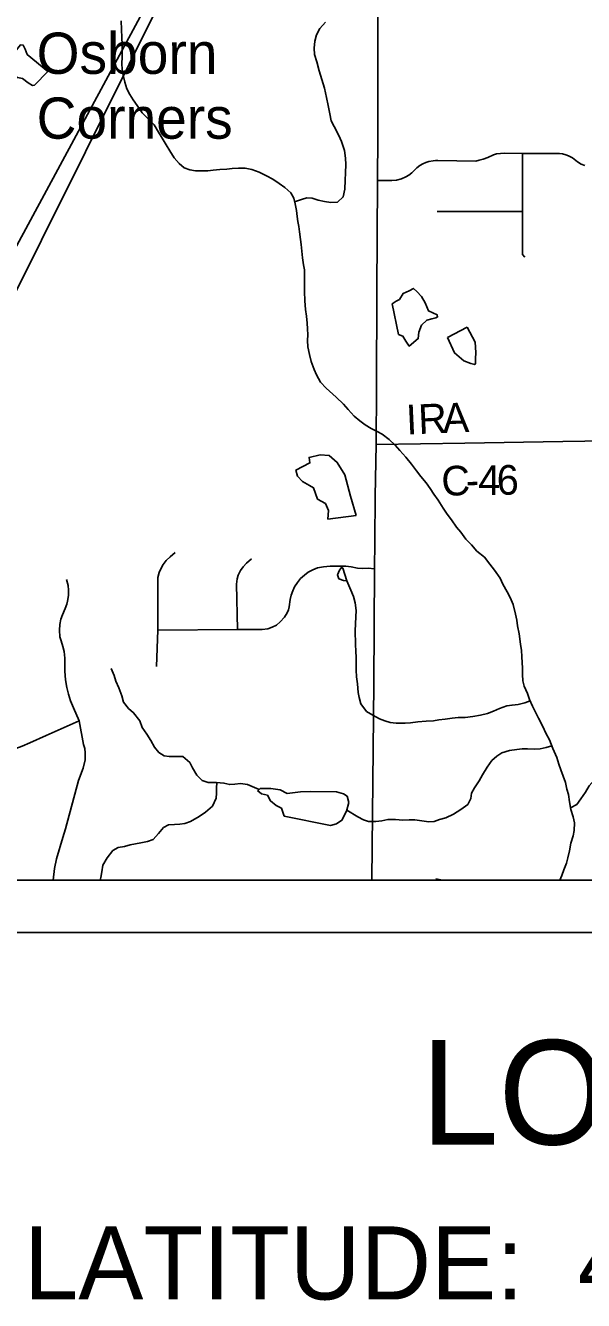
# Model space of a CAD drawing. Extents: x 0 to 34, y 0 to 22.
# Drawn here: x 3.669 to 4.739, y 13.295 to 15.737 of the extents above; entities that cross this region are included whole.
import ezdxf

# ---------------------------------------------------------------- set-up
doc = ezdxf.new("R2010")
doc.units = 0
for name, color, linetype in [('Default', 7, 'Continuous'), ('GM_X_County_Road', 7, 'Continuous'), ('GM_X_County_Road_Text', 7, 'Continuous'), ('GM_X_Minor_Lake', 7, 'Continuous'), ('GM_X_Minor_River', 7, 'Continuous'), ('GM_X_Township_Road', 7, 'Continuous'), ('GM_X_Unincorporated_Text', 7, 'Continuous'), ('SH_Cut_Line', 7, 'Continuous'), ('SH_Data', 7, 'Continuous'), ('SH_Text', 7, 'Continuous')]:
    doc.layers.add(name, color=color, linetype=linetype)

msp = doc.modelspace()

# ---------------------------------------------------------------- linework, layer by layer
at = {"layer": 'Default'}
msp.add_lwpolyline([(3.2815, 15.7537), (3.2811, 15.7294), (3.2832, 14.8896), (3.2841, 14.501), (3.2822, 14.2781), (3.2808, 14.1155), (3.2807, 14.1), (8.4439, 14.1), (8.4391, 14.4529), (8.4328, 14.555), (8.4328, 14.5554), (8.4608, 15.4787), (8.4608, 15.9241)], dxfattribs=at)
at = {"layer": 'GM_X_County_Road'}
for points in [[(4.3329, 14.1), (4.3329, 14.1015), (4.3366, 14.4752), (4.338, 14.6961), (4.3387, 14.7484), (4.3392, 14.8357), (4.3412, 14.9346), (4.3421, 15.043), (4.3424, 15.2273), (4.3441, 15.44), (4.3442, 15.525), (4.3442, 15.6692), (4.3448, 15.8518)], [(4.3412, 14.9346), (4.511, 14.937), (4.6987, 14.9398), (4.9098, 14.943), (5.086, 14.9444), (5.2239, 14.9463), (5.3069, 14.9479), (5.4298, 14.9489), (5.5067, 14.9509), (5.635, 14.953), (5.7464, 14.9549), (5.7732, 14.955), (5.875, 14.9557)]]:
    msp.add_lwpolyline(points, dxfattribs=at)
at = {"layer": 'GM_X_Minor_Lake'}
for points in [[(3.6727, 15.6811), (3.6688, 15.6914), (3.6653, 15.6989), (3.66, 15.7), (3.6353, 15.6682), (3.6403, 15.6531), (3.6465, 15.6421), (3.6541, 15.6373), (3.6636, 15.6351), (3.6747, 15.6268), (3.6831, 15.622), (3.6865, 15.6224), (3.7121, 15.6488)], [(3.7121, 15.6488), (3.6727, 15.6811)], [(4.3838, 15.1449), (4.3925, 15.142), (4.3979, 15.1321), (4.4048, 15.1227), (4.4218, 15.1373), (4.4228, 15.1495), (4.4284, 15.1628), (4.4385, 15.1724), (4.448, 15.1752), (4.4556, 15.1768), (4.459, 15.1787), (4.4582, 15.1825), (4.4414, 15.1903), (4.4352, 15.2058), (4.4283, 15.2175), (4.4191, 15.2273), (4.4126, 15.2333), (4.4043, 15.2287), (4.3933, 15.2237), (4.3858, 15.2122), (4.3794, 15.2091), (4.3718, 15.2037)], [(4.3718, 15.2037), (4.3838, 15.1449)], [(4.4779, 15.139), (4.4911, 15.1098), (4.5094, 15.0948), (4.5228, 15.0893), (4.53, 15.0874), (4.5315, 15.0897), (4.5314, 15.0981), (4.5321, 15.1106), (4.5311, 15.13), (4.5153, 15.1591)], [(4.5153, 15.1591), (4.4779, 15.139)], [(4.303, 14.7981), (4.2921, 14.8352), (4.2811, 14.8761), (4.2668, 14.8999), (4.2515, 14.9131), (4.2341, 14.9148), (4.2129, 14.9097), (4.2145, 14.8991), (4.1876, 14.8855), (4.1908, 14.8738), (4.2004, 14.8632), (4.2133, 14.8561), (4.221, 14.8516), (4.2291, 14.8297), (4.244, 14.8211), (4.2498, 14.8082), (4.2488, 14.7911)], [(4.2488, 14.7911), (4.303, 14.7981)], [(4.2774, 14.6976), (4.2747, 14.6987), (4.271, 14.6937), (4.2673, 14.6849), (4.27, 14.6774), (4.2784, 14.6736), (4.2852, 14.6733)], [(4.2852, 14.6733), (4.2774, 14.6976)], [(4.2541, 14.2046), (4.2655, 14.2081), (4.2757, 14.2147), (4.2843, 14.2319), (4.2887, 14.2486), (4.2855, 14.2608), (4.2786, 14.2656), (4.2653, 14.2693), (4.2148, 14.27), (4.1966, 14.2694), (4.1709, 14.2658), (4.1575, 14.2732), (4.1397, 14.2753), (4.1192, 14.2759), (4.1143, 14.2709), (4.1215, 14.2657), (4.1329, 14.2627), (4.1391, 14.2518), (4.1498, 14.2432), (4.1597, 14.2379), (4.1652, 14.2224)], [(4.1652, 14.2224), (4.2541, 14.2046)]]:
    msp.add_lwpolyline(points, dxfattribs=at)
at = {"layer": 'GM_X_Minor_River'}
for points in [[(4.2039, 15.2272), (4.2038, 15.2428), (4.2037, 15.2553), (4.2039, 15.269), (4.2023, 15.2785), (4.1999, 15.2921), (4.1974, 15.3172), (4.1966, 15.327), (4.1945, 15.3415), (4.1929, 15.3521), (4.1913, 15.3616), (4.1901, 15.371), (4.1885, 15.3824), (4.1861, 15.3949), (4.1833, 15.4063), (4.1775, 15.4161), (4.1661, 15.4263), (4.1557, 15.4342), (4.1435, 15.4424), (4.1309, 15.4491), (4.1172, 15.4558), (4.1031, 15.461), (4.0906, 15.4632), (4.0777, 15.4638), (4.0655, 15.463), (4.0549, 15.4617), (4.042, 15.4608), (4.0291, 15.4596), (4.0185, 15.4587), (3.9954, 15.4585), (3.984, 15.4603), (3.9737, 15.4644), (3.9641, 15.4723), (3.9546, 15.4832), (3.9461, 15.4964), (3.9388, 15.5081), (3.9314, 15.521), (3.9245, 15.5323), (3.9157, 15.5463), (3.9049, 15.5572), (3.8927, 15.5696), (3.8831, 15.5836), (3.8758, 15.5945), (3.8696, 15.6047), (3.8638, 15.6157), (3.8599, 15.6282), (3.8564, 15.6415), (3.8547, 15.6528), (3.8543, 15.6635), (3.8545, 15.6764), (3.8548, 15.6908), (3.8547, 15.7003), (3.8542, 15.7136), (3.8537, 15.7288), (3.8528, 15.7455)], [(4.1851, 15.3991), (4.1981, 15.4038), (4.2087, 15.4069), (4.2186, 15.4059), (4.23, 15.4022), (4.2426, 15.3997), (4.2544, 15.3979), (4.2669, 15.3987), (4.2782, 15.4083), (4.2811, 15.4236), (4.2817, 15.4403), (4.2827, 15.4544), (4.2833, 15.4703), (4.2824, 15.4825), (4.2804, 15.4973), (4.2749, 15.5143), (4.2695, 15.526), (4.261, 15.5431), (4.2552, 15.554), (4.2524, 15.5677), (4.2493, 15.5836), (4.2461, 15.5991), (4.2421, 15.6166), (4.237, 15.6333), (4.2323, 15.6499), (4.2273, 15.667), (4.2233, 15.6814), (4.2225, 15.6935), (4.2235, 15.7068), (4.2268, 15.7186), (4.2335, 15.7312), (4.244, 15.7431)], [(4.6929, 14.1), (4.6967, 14.1089), (4.7008, 14.1196), (4.7056, 14.1325), (4.7086, 14.1428), (4.7115, 14.1565), (4.7144, 14.171), (4.7184, 14.1847), (4.7206, 14.195), (4.7212, 14.2098), (4.7185, 14.2215), (4.7142, 14.2352), (4.7114, 14.2503), (4.7097, 14.264), (4.7066, 14.2746), (4.7038, 14.2871), (4.6953, 14.3113), (4.6914, 14.3219), (4.6871, 14.3352), (4.6797, 14.3519), (4.6731, 14.3685), (4.6666, 14.3817), (4.6604, 14.3946), (4.6523, 14.4101), (4.6407, 14.4335), (4.6349, 14.446), (4.631, 14.4574), (4.6251, 14.4714), (4.6224, 14.4816), (4.6219, 14.4941), (4.6218, 14.5059), (4.6209, 14.5169), (4.6205, 14.5279), (4.6196, 14.5408), (4.618, 14.5515), (4.6167, 14.5625), (4.6151, 14.572), (4.6123, 14.5871), (4.6107, 14.5981), (4.6083, 14.6095), (4.6036, 14.6277), (4.5982, 14.6413), (4.5924, 14.6523), (4.5839, 14.6666), (4.5789, 14.6787), (4.5677, 14.6938), (4.5593, 14.7055), (4.5485, 14.7183), (4.5344, 14.73), (4.524, 14.742), (4.5133, 14.7533), (4.5037, 14.7662), (4.4953, 14.776), (4.4853, 14.7899), (4.4772, 14.8012), (4.4699, 14.8126), (4.4599, 14.8277), (4.4518, 14.8394), (4.4449, 14.8503), (4.4372, 14.8609), (4.4268, 14.873), (4.4188, 14.8839), (4.4088, 14.8967), (4.3984, 14.9103), (4.3869, 14.9227), (4.3777, 14.9333), (4.3662, 14.9442), (4.3529, 14.9543), (4.3433, 14.9595), (4.3319, 14.9651), (4.3201, 14.9719), (4.3101, 14.9797), (4.299, 14.9884), (4.2875, 15.0012), (4.2787, 15.0117), (4.2649, 15.0249), (4.2458, 15.0422), (4.2347, 15.0539), (4.227, 15.0679), (4.2223, 15.0777), (4.2169, 15.0936), (4.2133, 15.1069), (4.2102, 15.1213), (4.2097, 15.1338), (4.2103, 15.1444), (4.2099, 15.1558), (4.2094, 15.1665), (4.2077, 15.1801), (4.2057, 15.1926), (4.2044, 15.2093), (4.2039, 15.2272)], [(4.636, 14.4436), (4.6262, 14.4395), (4.6133, 14.4367), (4.6016, 14.4355), (4.5917, 14.4338), (4.5773, 14.4291), (4.566, 14.4237), (4.5543, 14.4194), (4.541, 14.4163), (4.5266, 14.4135), (4.5115, 14.4118), (4.4986, 14.4113), (4.4868, 14.4101), (4.4732, 14.4084), (4.4614, 14.4068), (4.4508, 14.4052), (4.4371, 14.4047), (4.4212, 14.403), (4.4072, 14.4013), (4.3966, 14.4005), (4.3795, 14.4007), (4.3681, 14.4021), (4.3578, 14.405), (4.3479, 14.4091), (4.3346, 14.4158), (4.3228, 14.4233), (4.312, 14.4377), (4.3085, 14.4498), (4.3069, 14.4593), (4.3052, 14.476), (4.3039, 14.4893), (4.3027, 14.5022), (4.3029, 14.5158), (4.3028, 14.5272), (4.3024, 14.5382), (4.3015, 14.5519), (4.3012, 14.5777), (4.3015, 14.591), (4.3021, 14.6043), (4.3028, 14.6165), (4.3011, 14.6313), (4.2976, 14.6434), (4.2926, 14.6552), (4.2852, 14.6733)], [(4.1172, 14.2739), (4.0948, 14.2833), (4.0811, 14.2851), (4.0705, 14.2842), (4.0607, 14.283), (4.0496, 14.2859), (4.0356, 14.2873), (4.0196, 14.2871), (4.0082, 14.2908), (3.9979, 14.3014), (3.9894, 14.3153), (3.984, 14.3255), (3.9706, 14.3368), (3.9444, 14.3366), (3.9349, 14.338), (3.9246, 14.3447), (3.9169, 14.3545), (3.9096, 14.3678), (3.9019, 14.3799), (3.8931, 14.3927), (3.8884, 14.4052), (3.8765, 14.4206), (3.8669, 14.4285), (3.8573, 14.441), (3.8542, 14.4531), (3.8484, 14.4682), (3.8426, 14.4811), (3.8391, 14.4921), (3.8336, 14.5053)], [(4.6776, 14.3572), (4.6672, 14.354), (4.6554, 14.3516), (4.6448, 14.3508), (4.6315, 14.3514), (4.6209, 14.3517), (4.6107, 14.3504), (4.597, 14.3484), (4.5823, 14.3441), (4.5725, 14.3375), (4.5627, 14.3291), (4.5537, 14.3165), (4.5451, 14.3016), (4.5387, 14.2901), (4.5294, 14.2767), (4.5238, 14.2664), (4.5224, 14.2565), (4.5168, 14.2451), (4.5032, 14.2351), (4.4896, 14.2262), (4.4745, 14.2192), (4.4624, 14.2161), (4.4525, 14.2122), (4.4423, 14.2117), (4.429, 14.2139), (4.4153, 14.2153), (4.4047, 14.2155), (4.3926, 14.215), (4.3781, 14.216), (4.3637, 14.2163), (4.352, 14.2139), (4.3406, 14.2127), (4.3269, 14.2125), (4.3167, 14.2155), (4.306, 14.2211), (4.2848, 14.234)], [(4.7135, 14.2389), (4.7259, 14.2452), (4.7334, 14.2555), (4.7423, 14.2685), (4.7494, 14.2807), (4.7588, 14.2914), (4.7721, 14.2893), (4.7816, 14.2875), (4.7927, 14.2861), (4.8063, 14.2862), (4.8161, 14.2927), (4.8263, 14.3016), (4.8368, 14.3134), (4.8348, 14.3248), (4.8328, 14.3347), (4.8323, 14.3468), (4.8341, 14.3579), (4.8444, 14.369)], [(4.0363, 14.2872), (4.0357, 14.2763), (4.0354, 14.2668), (4.0347, 14.2573), (4.0276, 14.242), (4.0145, 14.2301), (4.0024, 14.222), (3.9858, 14.2124), (3.9748, 14.2088), (3.965, 14.2072), (3.9551, 14.2067), (3.9437, 14.2063), (3.9339, 14.2008), (3.9245, 14.1897), (3.914, 14.1782), (3.9034, 14.174), (3.8905, 14.1716), (3.8803, 14.1699), (3.8701, 14.1676), (3.8591, 14.1648), (3.847, 14.1624), (3.8368, 14.1566), (3.8259, 14.1428), (3.8177, 14.1291), (3.8155, 14.1158), (3.8137, 14.1051), (3.8123, 14.1)]]:
    msp.add_lwpolyline(points, dxfattribs=at)
at = {"layer": 'GM_X_Township_Road'}
for p, q in [((4.4582, 15.3805), (4.6214, 15.3807)), ((4.4555, 14.1028), (4.4685, 14.1))]:
    msp.add_line(p, q, dxfattribs=at)
for points in [[(4.3441, 15.44), (4.3714, 15.4402), (4.3804, 15.4407), (4.3901, 15.443), (4.3983, 15.4471), (4.4036, 15.4503), (4.4096, 15.4547), (4.4193, 15.4642), (4.4249, 15.4687), (4.4304, 15.472), (4.4364, 15.4745), (4.4421, 15.4764), (4.4506, 15.4778), (4.4548, 15.4782), (4.4597, 15.4784), (4.5322, 15.4771), (4.5386, 15.4787), (4.5462, 15.4808), (4.555, 15.4842), (4.5663, 15.4893), (4.572, 15.4909), (4.5792, 15.4918), (4.5878, 15.492), (4.6218, 15.4913), (4.6925, 15.4914), (4.6983, 15.4907), (4.7045, 15.489), (4.71, 15.487), (4.7172, 15.4833), (4.7273, 15.4755), (4.7342, 15.4713), (4.7409, 15.4685)], [(4.6262, 15.293), (4.6218, 15.2985), (4.6214, 15.3807), (4.6218, 15.4913)], [(3.9206, 14.5095), (3.9233, 14.5786), (3.9231, 14.6795), (3.9254, 14.6892), (3.9291, 14.6977), (3.933, 14.7046), (3.9392, 14.712), (3.9464, 14.7194), (3.9563, 14.7274)], [(3.9233, 14.5786), (4.0754, 14.5798), (4.123, 14.5798), (4.1339, 14.5811), (4.1419, 14.5846), (4.1502, 14.5883), (4.1574, 14.5945), (4.1657, 14.6037), (4.1705, 14.6122), (4.1735, 14.6175), (4.1747, 14.6238), (4.1767, 14.6374), (4.1786, 14.6461), (4.1816, 14.6539), (4.185, 14.6615), (4.1908, 14.6703), (4.1963, 14.6777), (4.2037, 14.6841), (4.2113, 14.6897), (4.2198, 14.6943), (4.229, 14.6979), (4.2401, 14.7), (4.2532, 14.7012), (4.2832, 14.7012), (4.2933, 14.6998), (4.3055, 14.6977), (4.3154, 14.697), (4.326, 14.6975), (4.338, 14.6961)], [(4.0754, 14.5798), (4.0735, 14.6671), (4.0749, 14.677), (4.0772, 14.6844), (4.0816, 14.6929), (4.0862, 14.6998), (4.0929, 14.7072), (4.1025, 14.7157)], [(3.7725, 14.4052), (3.7612, 14.4303), (3.7559, 14.4434), (3.7518, 14.4565), (3.7487, 14.4692), (3.7463, 14.4837), (3.7449, 14.5004), (3.7447, 14.5142), (3.7446, 14.5255), (3.7435, 14.538), (3.7412, 14.5477), (3.7378, 14.5583), (3.7355, 14.5658), (3.7346, 14.5791), (3.7352, 14.5895), (3.7369, 14.5998), (3.7404, 14.6083), (3.7452, 14.6202), (3.7485, 14.6289), (3.7499, 14.6342), (3.7518, 14.6455), (3.752, 14.6557), (3.751, 14.6646), (3.7482, 14.6758)], [(3.5093, 14.3834), (3.5168, 14.3773), (3.5248, 14.3716), (3.5349, 14.3655), (3.5457, 14.36), (3.5495, 14.3583), (3.5662, 14.3524), (3.5774, 14.3496), (3.5905, 14.3474), (3.6014, 14.3465), (3.6102, 14.3464), (3.6221, 14.347), (3.6314, 14.3481), (3.6413, 14.3499), (3.6508, 14.3524), (3.6632, 14.3566), (3.6778, 14.3629), (3.7091, 14.3769), (3.7725, 14.4052)], [(3.7224, 14.1), (3.7253, 14.1222), (3.729, 14.1407), (3.7409, 14.1816), (3.7458, 14.1984), (3.7712, 14.2907), (3.7797, 14.3145), (3.7835, 14.3302), (3.7841, 14.3377), (3.7839, 14.3436), (3.7829, 14.3521), (3.7809, 14.3601), (3.7725, 14.4052)]]:
    msp.add_lwpolyline(points, dxfattribs=at)
at = {"layer": 'SH_Cut_Line'}
msp.add_lwpolyline([(3.2807, 14.1), (8.9, 14.1), (8.9, 20.9), (3.2826, 20.9), (3.2843, 20.6124), (3.2845, 20.5998), (3.2888, 19.8918), (3.2901, 19.68), (3.2904, 19.1173), (3.2907, 18.4315), (3.2837, 17.3796), (3.2835, 17.0107), (3.2832, 16.3898), (3.2829, 15.8433), (3.2815, 15.7537), (3.2811, 15.7294), (3.2832, 14.8896), (3.2841, 14.501), (3.2822, 14.2781), (3.2808, 14.1155)], close=True, dxfattribs=at)
at = {"layer": 'SH_Data'}
for p, q in [((2.1, 14.1), (8.9, 14.1)), ((2, 14), (9, 14))]:
    msp.add_line(p, q, dxfattribs=at)
at = {"layer": 'SH_Text'}
msp.add_lwpolyline([(2.8604, 13.8477), (4.2041, 16.3374), (2.8604, 13.6417)], close=True, dxfattribs=at)

# ---------------------------------------------------------------- texts
at = {"layer": 'GM_X_County_Road_Text'}
for s, rotation, p in [('I', 2.6004, (4.3998, 14.9533)), ('R', 2.5964, (4.4231, 14.9543)), ('A', 2.1278, (4.4696, 14.9564)), ('C', 2.4089, (4.4674, 14.8356)), ('4', 0.0885, (4.5368, 14.8379)), ('6', 0.8554, (4.5726, 14.8379)), ('-', 0.9133, (4.5136, 14.8375))]:
    msp.add_text(s, height=0.0568, rotation=rotation, dxfattribs=at).set_placement(p)
at = {"layer": 'GM_X_Unincorporated_Text'}
for s, p in [('Osborn', (3.6908, 15.6441)), ('Corners', (3.6908, 15.5199))]:
    msp.add_text(s, height=0.07898, rotation=0, dxfattribs=at).set_placement(p)
at = {"layer": 'SH_Text'}
for s, height, p in [('LOCATION MAP', 0.2, (4.4269, 13.5938)), ('NB SITE LATITUDE:  41°12\'30" N   LONGITUDE:  81°40\'10" W', 0.14, (2.8862, 13.2971))]:
    msp.add_text(s, height=height, dxfattribs=at).set_placement(p)

doc.saveas('drawing.dxf')
